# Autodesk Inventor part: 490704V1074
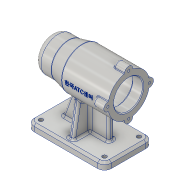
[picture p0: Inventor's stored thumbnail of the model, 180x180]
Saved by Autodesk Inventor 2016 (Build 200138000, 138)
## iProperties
Created: 2019-07
Part Number: 490704V1074
Material: 알루미늄 6061
Document SubType Name: Modeling
Designer: 605-12
Density: 2.7 g/cm^3
Appearance: 알루미늄 - 평지
Mass: 644.389 g
Surface Area: 654.079 cm^2
Volume: 238.663 cm^3
Author: 605-12
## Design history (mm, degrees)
sketch "스케치1"
  geometry: L1 (-56, 0)-(56, 0); L2 (41, 21)-(56, 21); L3 (41, 21)-(41, 24); L4 (41, 24)-(-13, 24); L5 (-13, 24)-(-13, 21); L6 (-13, 21)-(-25, 21); L7 (-25, 21)-(-25, 17.5); L8 (-25, 17.5)-(-43, 17.5); L9 (-43, 17.5)-(-43, 16); L10 (-43, 16)-(-47, 16); L11 (-47, 16)-(-47, 10.5); L12 (-47, 10.5)-(-50, 10.5); L13 (-50, 10.5)-(-50, 0); L14 (56, 21)-(56, 30); L15 (56, 30)-(-11, 30); L16 (-11, 30)-(-31, 25); L17 (-31, 25)-(-56, 25); L18 (-56, 25)-(-56, 0); 1 further point
  constraints: 36 end point, 7 vertical, 5 perpendicular, 3 parallel, 2 horizontal, 1 midpoint, 1 point on line, 1 vertical alignment
  dimensions: "d0" = 112 distance of L1.start L1.end; "d1" = 56 distance of point (0, 0) L1.start; "d2" = 42 diameter of L2 L1; "d3" = 15 distance of L2.start L2.end; "d4" = 54 distance of L3.end L4.end; "d5" = 48 diameter of L4 L1; "d6" = 42 diameter of L6 L1; "d7" = 12 distance of L5.end L6.end; "d8" = 18 distance of L7.end L8.end; "d9" = 35 diameter of L8 L1; "d10" = 32 diameter of L10 L1; "d11" = 4 distance of L9.end L10.end; "d12" = 3 distance of L11.end L12.end; "d13" = 21 diameter of L12 L1; "d15" = 45 distance from line of L15.end L18; "d16" = 25 distance of L16.end L17.end; "d17" = 60 diameter of L15 L1; "d18" = 50 diameter of L17 L1
revolve "회전1" sketch "스케치1" stored, may be unused: angle "d19" = 90 deg
sketch "스케치2"
  geometry: L1 (-56, -70)-(56, -70); L2 (56, -70)-(56, -80); L3 (56, -80)-(-56, -80); L4 (-56, -80)-(-56, -70); 1 further point
  constraints: 8 end point, 2 parallel, 1 horizontal, 1 perpendicular
  dimensions: "d20" = 80 distance from line of point (0, 0) L3; "d21" = 112 distance of L2.end L3.end; "d22" = 10 distance of L3.end L1.start; "d23" = 56 distance from line of point (0, 0) L4
extrude "돌출1" join sketch "스케치2" stored distance "d24" = 70; taper "d25" = 0 deg
sketch "스케치3"
  geometry: L1 (-70, -35)-(-70, 35) reference; L2 (-22.666, 19.654)-(-70, 28); L3 (-22.666, -19.654)-(-70, -28); L4 (-70, 35)-(-80, 35) reference; L5 (-80, -35)-(-70, -35) reference; A1 r 30 centre (0, 0) between (-22.666, 19.654) and (-22.666, -19.654) reference; 1 further point
  constraints: 4 end point, 2 point on circle, 2 point on line
  dimensions: "d26" = 100 deg angle of L2 L1; "d27" = 7 distance from line of L2.end L4; "d28" = 7 distance from line of L5 L3.end; "d29" = 100 deg angle of L1 L3
extrude "돌출2" join sketch "스케치3" stored distance "d30" = 8; taper "d31" = 0 deg
sketch "스케치4"
  geometry: L1 (-11, -30)-(56, -30) reference; L2 (-56, -70)-(56, -70) reference; L3 (31, -30)-(31, -34.292); L4 (31, -34.292)-(31, -70); L5 (56, -70)-(56, -80) reference; 1 further point
  constraints: 4 end point, 3 point on line, 1 perpendicular
  dimensions: "d32" = 25 distance between parallel lines of L5 L4
feature "리브1" sketch "스케치4" dims "d33" = 1, "d34" = 8, "d35" = 0, "d36" = 0, "d37" = 1, "d38" = 1
sketch "스케치5"
  geometry: L1 (-31, -25)-(-11, -30) reference; L2 (-56, -70)-(56, -70) reference; L3 (-11, -30)-(56, -30) reference; L4 (-20.57, -27.607)-(-36, -70); L5 (-56, -80)-(-56, -70) reference; 1 further point
  constraints: 2 end point, 2 point on line
  dimensions: "d39" = 20 distance from line of L5 L4.end; "d40" = 110 deg angle of L2 L4
feature "리브2" sketch "스케치5" dims "d41" = 1, "d42" = 8, "d43" = 0, "d44" = 0, "d45" = 1, "d46" = 1
fillet "모깎기1" dims "d47" = 10
sketch "스케치7"
  geometry: L1 (92, 70)-(0, 70) reference; L2 (102, 10)-(102, 60) reference; L3 (0, 0)-(92, 0) reference; L4 (-10, 10)-(-10, 60) reference; A1 r 10 centre (0, 60) between (0, 70) and (-10, 60) reference; A2 r 10 centre (92, 60) between (102, 60) and (92, 70) reference; A3 r 10 centre (92, 10) between (92, 0) and (102, 10) reference; A4 r 10 centre (0, 10) between (-10, 10) and (0, 0) reference; 1 further point
hole "구멍1" sketch "스케치7" at (0, 10), (0, 60), (92, 60), (92, 10) diameter "d48" = 6; stored, may be unused: countersink angle "d52" = 90 deg, drill point angle "d54" = 118 deg; dims "d49" = 6, "d50" = 4, "d51" = 2, "d53" = 8
sketch "스케치8"
  geometry: C1 r 21 at (0, 0) reference; A1 r 30 centre (0, 0) between (4, -29.732) and (-4, -29.732) reference; A2 r 30 centre (0, 0) between (4, -29.732) and (-4, -29.732) reference; A3 r 6 centre (0, 30) between (5.97, 29.4) and (-5.97, 29.4); A4 r 6 centre (0, 30) between (-5.97, 29.4) and (5.97, 29.4); 2 further points
  constraints: 7 point on circle, 2 centre point, 2 vertical alignment, 1 other
  dimensions: "d58" = 6 radius of A3
extrude "돌출3" join sketch "스케치8" distance "d59" = 16; taper "d60" = 0 deg
fillet "모깎기2" dims "d61" = 3
fillet "모깎기3" dims "d62" = 1
hole "구멍2" diameter "d65" = 3.242; stored, may be unused: countersink angle "d69" = 90 deg, drill point angle "d71" = 120 deg; dims "d63" = 10, "d64" = 10, "d66" = 8, "d67" = 4, "d68" = 2, "d70" = 11
node "작업 평면1"
sketch "스케치9"
  geometry: L1 (33.5, 30.171)-(33.5, 36) reference; 2 further points
  constraints: 1 horizontal alignment, 1 other
  dimensions: "d75" = 42 distance from line of L1 point (-8.5, 0)
feature "엠보싱1" sketch "스케치9" dims "d19" = 90 deg, "d76" = 0.5, "d77" = 0
fillet "모깎기4" dims "d78" = 10
fillet "모깎기6" dims "d80" = 3
fillet "모깎기7" dims "d81" = 3
fillet "모깎기8" dims "d82" = 3
fillet "모깎기9" dims "d83" = 3
chamfer "모따기1" distance "d84" = 1; stored, may be unused: second distance "d85" = 2, angle "d86" = 45 deg
fillet "모깎기10" dims "d87" = 0.3
fillet "모깎기11" dims "d88" = 3
chamfer "모따기2" distance "d89" = 3; stored, may be unused: second distance "d90" = 2, angle "d91" = 45 deg
fillet "모깎기12" dims "d92" = 3
node "솔리드1"
pattern_circular "원형 패턴1" dims "d73" = 360 deg
node "투영된 루프1"
node "투영된 루프2"
